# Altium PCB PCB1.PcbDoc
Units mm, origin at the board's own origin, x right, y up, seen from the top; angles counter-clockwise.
Board outline 152.4 x 101.6 mm, 2 copper layers (Top Layer, Bottom Layer); 11 components, 12 nets, 29 pads, 0 vias.
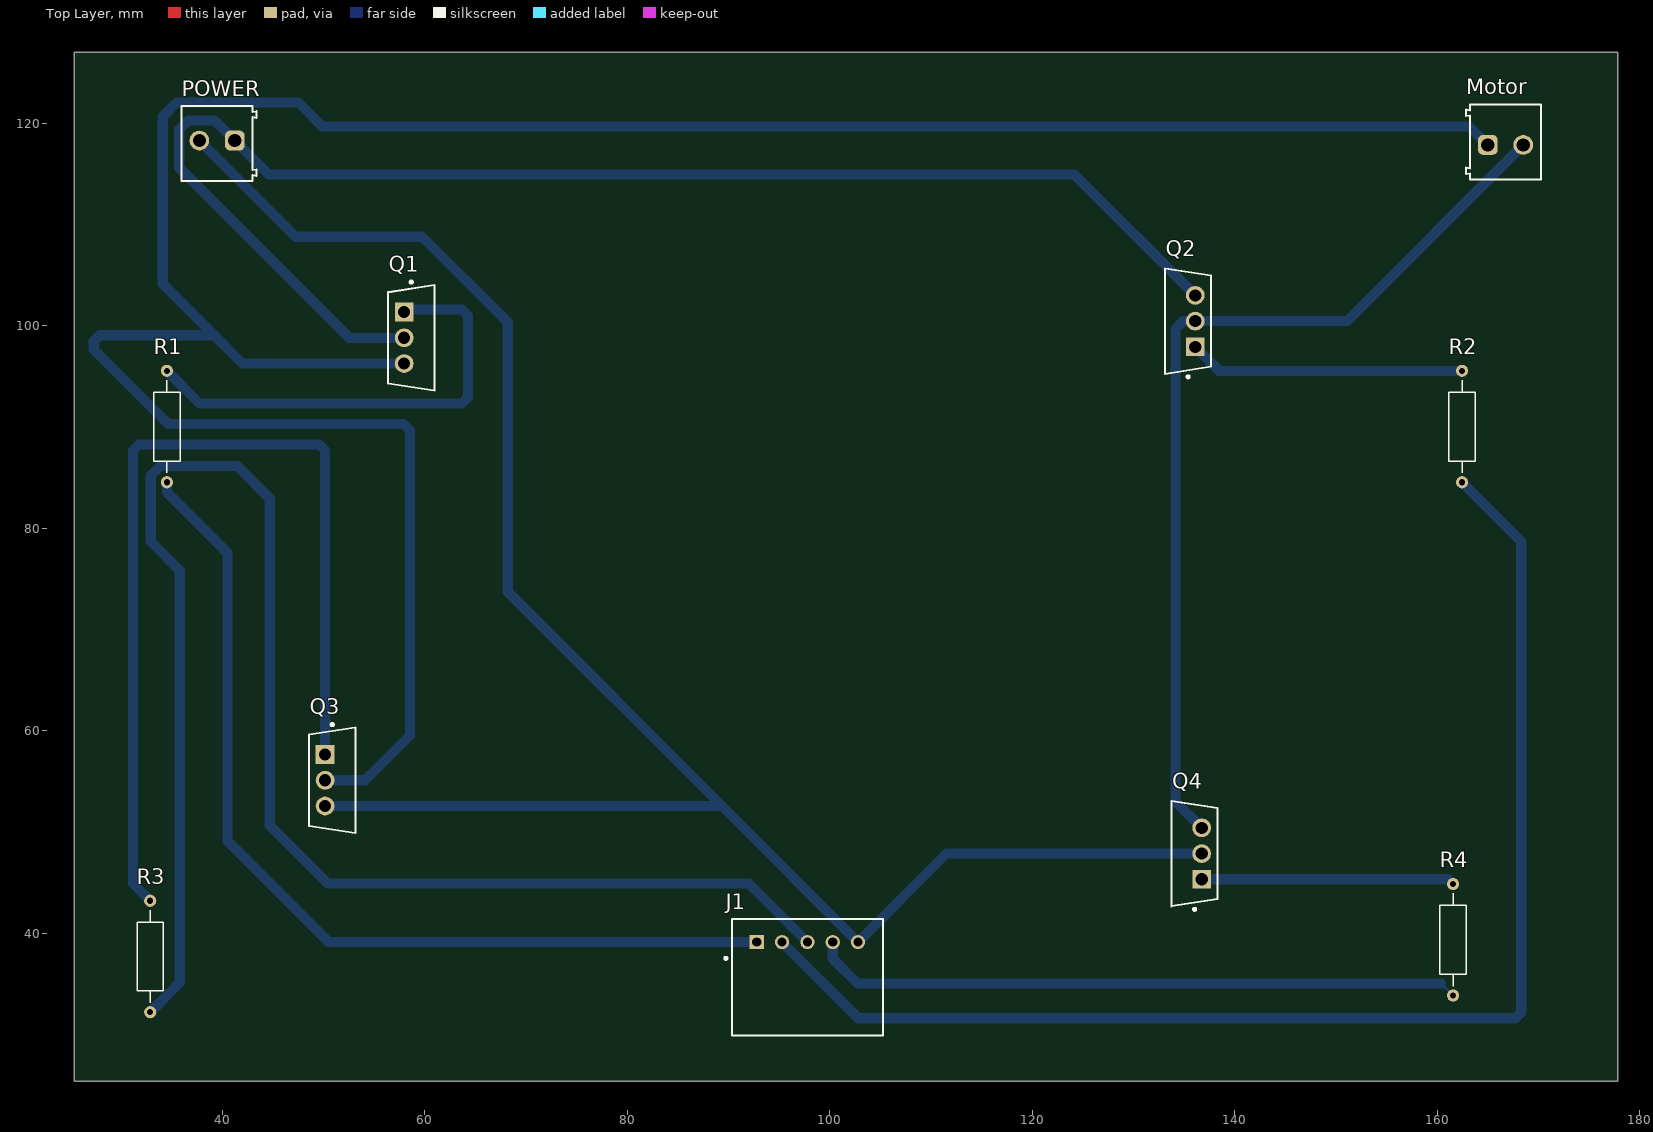
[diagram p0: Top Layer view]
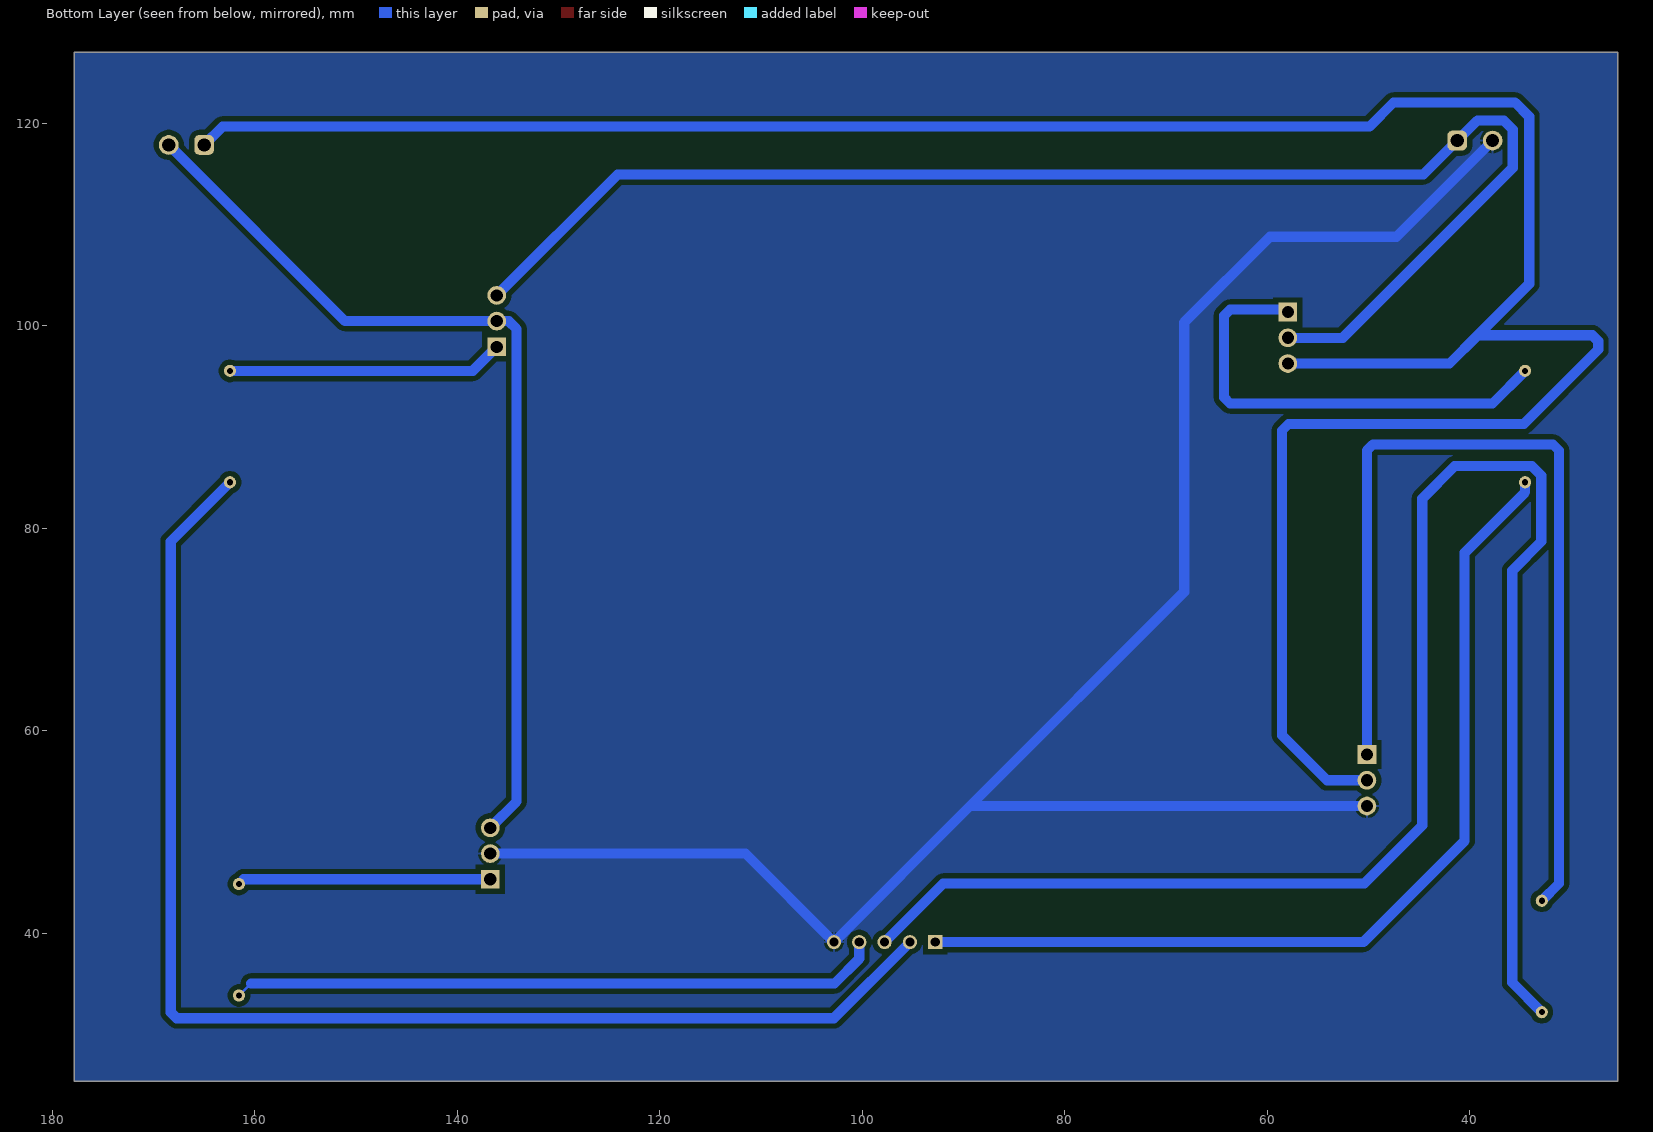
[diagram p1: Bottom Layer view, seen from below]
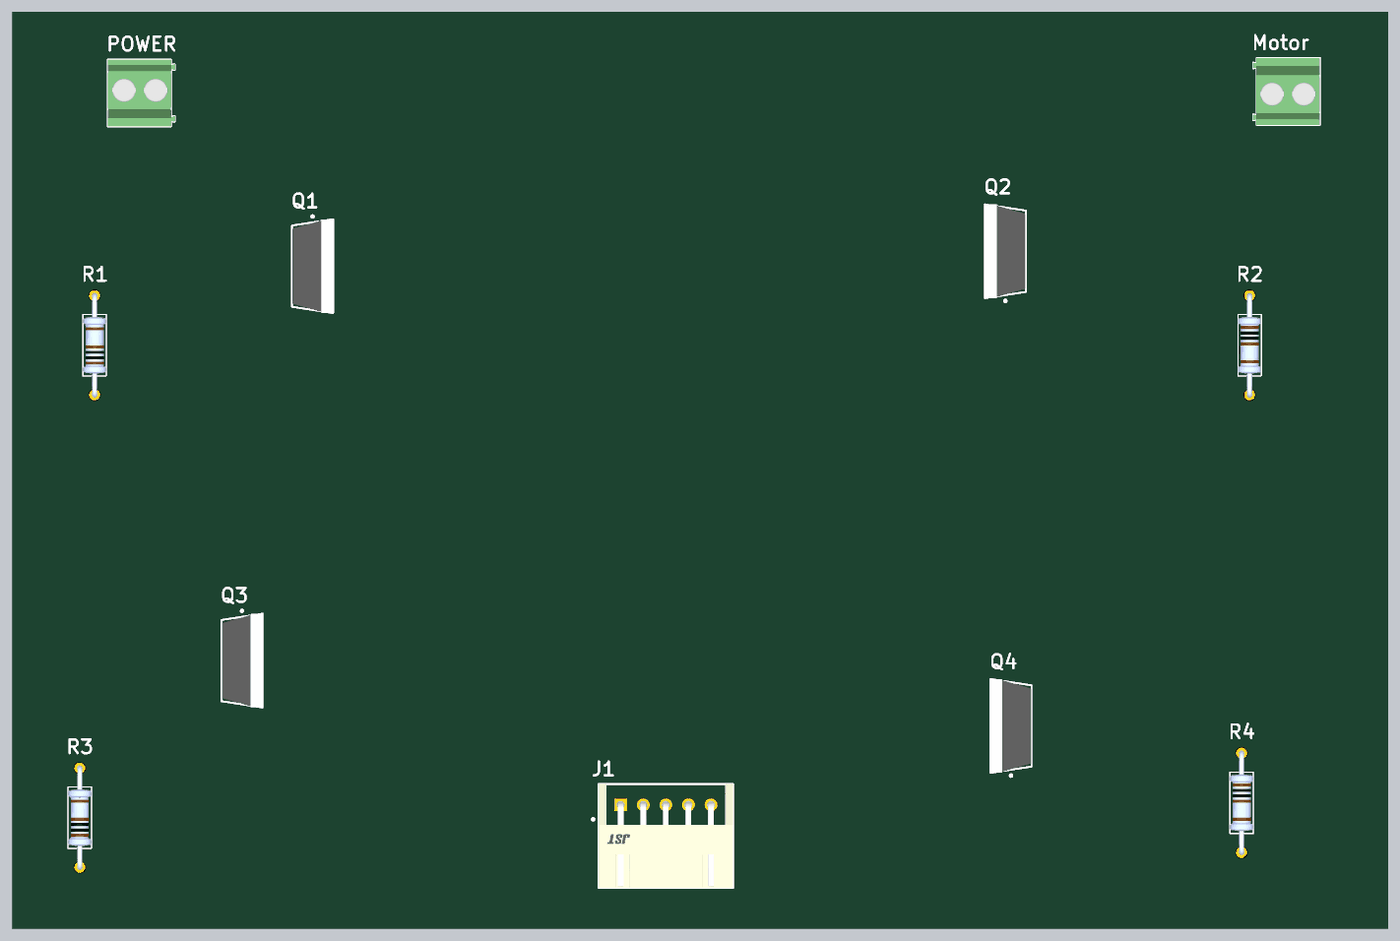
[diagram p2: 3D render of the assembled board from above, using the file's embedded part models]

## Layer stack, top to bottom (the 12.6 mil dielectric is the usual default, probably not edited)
Top Solder: solder mask 0.0102, Solder Resist, Dk 3.5
Top Layer: signal copper 0.0356
Dielectric 1: dielectric 0.32, FR-4, Dk 4.8
Bottom Layer: signal copper 0.0356
Bottom Solder: solder mask 0.0102, Solder Resist, Dk 3.5

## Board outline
25.4,25.4 177.8,25.4 177.8,127 25.4,127

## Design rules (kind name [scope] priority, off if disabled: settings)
Clearance [All] p1: gap=0.5 ignorepadtopadclearanceinfootprint=FALSE
PolygonConnect [All] p1: connectstyle=Relief reliefconductorwidth=0.254 reliefentries=4 polygonreliefangle="90 Angle" airgapwidth=0.254
RoutingVias [All] p1: holewidth=0.711 width=1.27 viastyle="Through Hole" minholewidth=0.711 minwidth=1.27 maxholewidth=0.711 maxwidth=1.27
SolderMaskExpansion [All] p1: expansion=0.102 istentingtop=FALSE
SupplyNets "Schematic Supply Nets_1" [InNet('VCC')] p1: voltage=0.000
SupplyNets "Schematic Supply Nets" [InNet('GND')] p2: voltage=0.000
Width [All] p1: maxlimit=1 minlimit=0.254 preferedwidth=0.7 toplayer_maxwidth=0.254 bottomlayer_minwidth=1 minimp=50.000000 maximp=50.000000 favimp=50.000000
30 further rules are at their usual default settings.

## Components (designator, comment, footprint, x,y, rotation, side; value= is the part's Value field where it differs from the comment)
J1 "S5B-XH-A(LF)(SN)" "JST Conncetor 5 pins" 97.79,35.687 r180 top
Motor "691214110002" "Terminal block" 166.723,118.156 r0 top
POWER "691214110002" "Terminal block" 39.497,117.983 r180 top
Q1 "IRF4905PBF" "Mosfet P-Ch" 58.674,98.806 r0 top
Q2 "IRF4905PBF" "Mosfet P-Ch" 135.382,100.457 r180 top
Q3 "IRLZ44NPbF" "MOSFET N-CH 55V 47A TO220AB" 50.87,55.118 r0 top
Q4 "IRLZ44NPbF" "MOSFET N-CH 55V 47A TO220AB" 136.017,47.879 r180 top
R1 "Resistor" Resistor 34.544,90.043 r90 top value=10K
R2 "Resistor" Resistor 162.433,90.043 r270 top value=10K
R3 "Resistor" Resistor 32.893,37.719 r90 top value=10K
R4 "Resistor" Resistor 161.544,39.37 r270 top value=10K

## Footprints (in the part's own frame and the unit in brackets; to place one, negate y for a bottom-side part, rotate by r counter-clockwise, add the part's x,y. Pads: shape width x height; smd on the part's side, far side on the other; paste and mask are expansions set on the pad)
"JST Conncetor 5 pins" [mm]
  rect 1.4x1.4 hole 0.9 paste-2539.97 mask+0: 1(5,-3.45)
  round 1.4 hole 0.9 paste-2539.97 mask+0: 2(2.5,-3.45) 3(0,-3.45) 4(-2.5,-3.45) 5(-5,-3.45)
  silkscreen extent -7.45,-5.75 8.17,5.75, body extent -7.55,-5.85 7.55,5.85, height 0.25
"MOSFET N-CH 55V 47A TO220AB" [mm]
  rect 1.85x1.85 hole 1.2 paste-2539.97 mask+0: 1(-0.705,2.54)
  round 1.85 hole 1.2 paste-2539.97 mask+0: 2(-0.705,0) 3(-0.705,-2.54)
  silkscreen extent -2.27,-5.2 2.27,5.62, body extent -2.37,-5.55 2.37,5.55, height 0.25
"Mosfet P-Ch" [mm] "FP-PG-TO220-3-MFG"
  rect 1.85x1.85 hole 1.2 paste-2539.97 mask+0: 1(-0.705,2.54)
  round 1.85 hole 1.2 paste-2539.97 mask+0: 2(-0.705,0) 3(-0.705,-2.54)
  silkscreen extent -2.27,-5.2 2.27,5.62, body extent -2.37,-5.55 2.37,5.55, height 0.25
Resistor [mm]
  round 1.2 hole 0.6: 1(-5.5,0) 2(5.5,0)
  silkscreen extent -4.58,-1.3 4.58,1.3, body extent -5.77,-1.3 5.77,1.3, height 2.6
"Terminal block" [mm] "3.50 mm Horizontal Entry Modular, 2p"
  rrect50% 1.95x1.95 hole 1.3: 1(-1.75,-0.3)
  round 1.95 hole 1.3: 2(1.75,-0.3)
  silkscreen extent -3.9,-3.7 3.5,3.7, body extent -3.95,-3.7 3.5,3.7, height 8.55

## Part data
J1: library part "Jst conncetor 5 pins", "CONN HEADER R/A 5POS 2.5MM", Color=Natural, Contact Resistance=10mR, Current Rating=3A, Flammability Rating="UL94 V-0", Insulation Resistance=1GR, Max Operating Temperature=85°C, Min Operating Temperature=-25°C, Voltage Rating=250V
Motor POWER: library part "Terminal block", Color="Blue, Green", Current=10A, Max Operating Temperature=105°C, Min Operating Temperature=-40°C, Voltage=300V
Q1 Q2: library part "Mosfet P-CH", "MOSFET P-CH 55V 74A TO-220AB", Case/Package=TO-220, Continuous Drain Current (ID)=74A, Drain to Source Breakdown Voltage=-55V, Drain to Source Resistance=20mR, Gate to Source Voltage (Vgs)=20V, Input Capacitance=3.4nF, Max Operating Temperature=175°C, Max Power Dissipation=200W, Min Operating Temperature=-55°C, Threshold Voltage=-4V
Q3 Q4: library part "MOSFET N-CH 55V 47A TO220AB", Case/Package=TO-220, Continuous Drain Current (ID)=47A, Drain to Source Breakdown Voltage=55V, Drain to Source Resistance=35mR, Gate to Source Voltage (Vgs)=16V, Input Capacitance=1.7nF, Max Operating Temperature=175°C, Max Power Dissipation=110W, Min Operating Temperature=-55°C, Threshold Voltage=2V
R1 R2 R3 R4: "10.2 kOhms Â±1% 0.25W, 1/4W Through Hole Resistor Axial - Metal Film", Package="Axial Yageo"

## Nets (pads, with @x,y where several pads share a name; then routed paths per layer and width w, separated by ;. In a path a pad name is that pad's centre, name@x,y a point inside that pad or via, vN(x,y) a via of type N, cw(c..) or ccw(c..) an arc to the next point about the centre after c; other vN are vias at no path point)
GND: J1.5 POWER.2 Q3.3 Q4.2 | length 190.1
  Bottom Layer w1: POWER.2 47.242,108.788 59.741,108.788 68.199,100.33 68.199,73.728 89.349,52.578 ; Q3.3 89.349,52.578 ; Q4.2 111.532,47.879 J1.5 89.349,52.578
MCU_1: J1.1 R1.1 | length 94.3
  Bottom Layer w1: R1.1 34.544,83.566 40.513,77.597 40.513,49.149 50.525,39.137 J1.1
MCU_2: J1.2 R2.2 | length 131.1
  Bottom Layer w1: J1.2 102.804,31.623 167.689,31.623 168.275,32.209 168.275,78.701 R2.2
MCU_3: J1.3 R3.1 | length 159
  Bottom Layer w1: R3.1 35.814,35.14 35.814,75.819 32.944,78.689 32.944,85.206 33.881,86.143 41.492,86.143 44.704,82.931 44.704,50.648 50.419,44.933 91.994,44.933 J1.3
MCU_4: J1.4 R4.2 | length 64.4
  Bottom Layer w0.254: 160.362,35.052 R4.2
  Bottom Layer w1: J1.4 100.29,37.505 102.743,35.052 160.362,35.052
NetMotor_1: Motor.1 Q1.3 Q3.2 | length 264.6
  Bottom Layer w1: Q3.2 54.102,55.118 58.547,59.563 58.547,89.662 57.912,90.297 34.671,90.297 27.322,97.646 27.322,98.474 27.908,99.06 39.218,99.06 ; Q1.3 56.032,96.266 42.012,96.266 39.218,99.06 ; Motor.1 163.17,119.659 49.911,119.659 47.533,122.038 35.525,122.038 34.138,120.65 34.138,104.14 39.218,99.06
NetMotor_2: Motor.2 Q2.2 Q4.3 | length 92.2
  Bottom Layer w1: Q4.3 134.137,53.004 134.137,99.695 134.899,100.457 Q2.2 151.074,100.457 Motor.2
NetQ1_1: Q1.1 R1.2 | length 46
  Bottom Layer w1: R1.2 37.758,92.329 63.676,92.329 64.262,92.915 64.262,101.005 63.676,101.59 58.213,101.59 Q1.1
NetQ2_1: Q2.1 R2.1 | length 27.3
  Bottom Layer w1: Q2.1 138.461,95.543 R2.1
NetQ3_1: Q3.1 R3.2 | length 94.6
  Bottom Layer w1: R3.2 31.194,44.918 31.194,87.679 31.78,88.265 49.579,88.265 50.165,87.679 Q3.1
NetQ4_1: Q4.1 R4.1 | length 25
  Bottom Layer w0.254: 161.075,45.339 R4.1
  Bottom Layer w1: Q4.1 161.075,45.339
VCC: POWER.1 Q1.2 Q2.3 | length 140.8
  Bottom Layer w1: Q1.2 52.553,98.806 35.763,115.595 35.763,119.38 36.652,120.269 39.261,120.269 POWER.1 44.595,114.935 124.149,114.935 Q2.3

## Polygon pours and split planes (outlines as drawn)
GND on Bottom Layer "GND_L02_P004" (solid, remove dead copper, pour order 4): 25.4,25.4 177.8,25.4 177.8,127 25.4,127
